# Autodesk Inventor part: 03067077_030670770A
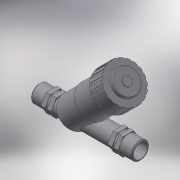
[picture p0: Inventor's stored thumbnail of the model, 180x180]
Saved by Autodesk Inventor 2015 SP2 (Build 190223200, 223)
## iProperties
Created: 2017-05
Part Number: 03067077_030670770A
Material: Generic
Description: PLASSON CHECK VALVE 3/4"
Document SubType Name: Modeling
Designer: KIM
Mass: 228.741 g
Surface Area: 415.565 cm^2
Volume: 228.741 cm^3
Density: 1 g/cm^3
Appearance: Default
Author: KIM
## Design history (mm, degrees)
derived "03067-03068.ipt"
feature "Solid1::03067-03068.ipt"
tag "TaggingFeature1"
body "Solid1"
other parameters: "d0" = 151, "d1" = 26.441, "d2" = 27, "d3" = 21.1528, "d4" = 18, "d5" = 18, "d6" = 15.1, "d8" = 1.51, "d12" = 0, "d14" = -7.55, "d15" = 3.02, "d16" = 0, "d17" = 36.288, "d18" = 5.184, "d20" = 45.36, "d21" = 135 deg, "d22" = 47.52, "d23" = 25.92, "d24" = 56.16, "d25" = 12.96, "d29" = 12.96, "d31" = 12.96, "d32" = 43.2, "d34" = 135 deg, "d35" = 2, "d36" = 86.4, "d39" = 52.85, "d40" = 1.92, "d80" = 54.4752, "d81" = 3.84, "d82" = 1.92, "d83" = 22.464, "d84" = 0, "d86" = 360 deg, "d88" = 0.96, "d90" = 1, "d91" = 96, "d92" = 1.296, "H_" = 151, "R_" = 26.441, "E_" = 27, "l_2" = 18, "A_" = 96, "d13" = 15.1, "d79" = 56.16
